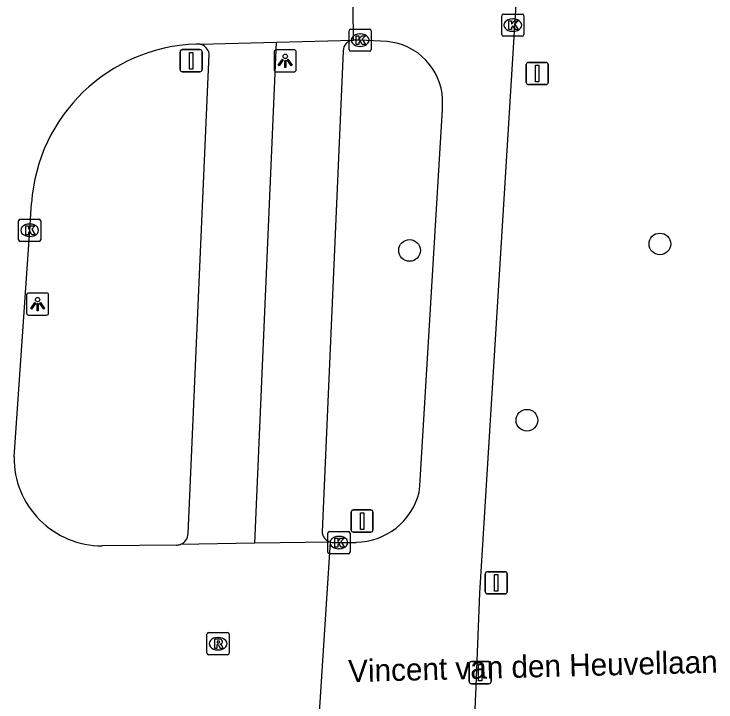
# Model space of a CAD drawing. Extents: x 161477 to 163040, y 383680 to 384868.
# Drawn here: x 161516.43 to 161548.07, y 384119.51 to 384150.53 of the extents above; entities that cross this region are included whole.
import ezdxf

# ---------------------------------------------------------------- set-up
doc = ezdxf.new("R2010")
doc.units = 0
for name, color, linetype in [('IMGEO_Afsluitpaal', 7, 'Continuous'), ('IMGEO_Boom', 7, 'Continuous'), ('IMGEO_Fietspad_open', 7, 'Continuous'), ('IMGEO_Kolk', 7, 'Continuous'), ('IMGEO_Lichtpunt', 7, 'Continuous'), ('IMGEO_Openbare_ruimte_label', 7, 'Continuous'), ('IMGEO_Rijbaan_lokaal_gesloten', 7, 'Continuous'), ('IMGEO_Rioolput', 7, 'Continuous'), ('IMGEO_Verkeersbordpaal', 7, 'Continuous'), ('IMGEO_Vlaggenmast', 7, 'Continuous'), ('IMGEO_Voetpad_open', 7, 'Continuous')]:
    doc.layers.add(name, color=color, linetype=linetype)

msp = doc.modelspace()

# ---------------------------------------------------------------- linework, layer by layer
at = {"layer": 'IMGEO_Afsluitpaal'}
for p, q in [((161537.045, 384121.33), (161537.835, 384121.33)), ((161537.835, 384121.33), (161537.045, 384121.33)), ((161536.945, 384120.43), (161536.945, 384121.23)), ((161536.945, 384121.23), (161536.945, 384120.43)), ((161537.935, 384121.23), (161537.935, 384120.43)), ((161537.935, 384120.43), (161537.935, 384121.23)), ((161537.835, 384120.33), (161537.045, 384120.33)), ((161537.045, 384120.33), (161537.835, 384120.33))]:
    msp.add_line(p, q, dxfattribs=at)
msp.add_lwpolyline([(161537.365, 384121.205), (161537.515, 384121.205), (161537.515, 384120.455), (161537.365, 384120.455), (161537.365, 384121.205)], dxfattribs=at)
for centre, start, end in [((161537.045, 384121.23), 90, 180), ((161537.045, 384121.23), 90, 180), ((161537.835, 384121.23), 0, 90), ((161537.835, 384121.23), 360, 90), ((161537.045, 384120.43), 180, 270), ((161537.045, 384120.43), 180, 270), ((161537.835, 384120.43), 270, 0), ((161537.835, 384120.43), 270, 0)]:
    msp.add_arc(centre, 0.1, start, end, dxfattribs=at)
at = {"layer": 'IMGEO_Boom'}
for centre in [(161545.537, 384140.162), (161534.259, 384139.873), (161539.548, 384132.212)]:
    msp.add_circle(centre, 0.489, dxfattribs=at)
at = {"layer": 'IMGEO_Fietspad_open'}
for points in [[(161527.282, 384126.677), (161528.268, 384149.264)], [(161524.274, 384127.108), (161525.225, 384148.724)]]:
    msp.add_lwpolyline(points, dxfattribs=at)
for centre, radius, start, end in [((161524.716, 384148.668), 0.512, 6.3303, 78.8532), ((161523.751, 384127.105), 0.523, 288.6131, 0.3768)]:
    msp.add_arc(centre, radius, start, end, dxfattribs=at)
at = {"layer": 'IMGEO_Kolk'}
for p, q in [((161538.41, 384149.606), (161538.41, 384150.458)), ((161538.485, 384150.532), (161539.337, 384150.532)), ((161539.411, 384150.458), (161539.411, 384149.606)), ((161538.898, 384150.312), (161538.923, 384150.312)), ((161531.604, 384149.853), (161532.456, 384149.853)), ((161531.529, 384148.927), (161531.529, 384149.779)), ((161532.017, 384149.633), (161532.042, 384149.633)), ((161532.53, 384149.779), (161532.53, 384148.927)), ((161539.337, 384149.532), (161538.485, 384149.532)), ((161538.921, 384149.752), (161538.896, 384149.752)), ((161532.456, 384148.853), (161531.604, 384148.853)), ((161532.04, 384149.073), (161532.015, 384149.073)), ((161516.714, 384141.279), (161517.566, 384141.279)), ((161516.639, 384140.353), (161516.639, 384141.205)), ((161517.127, 384141.059), (161517.152, 384141.059)), ((161517.64, 384141.205), (161517.64, 384140.353)), ((161517.15, 384140.499), (161517.125, 384140.499)), ((161517.566, 384140.279), (161516.714, 384140.279)), ((161530.574, 384126.269), (161530.574, 384127.121)), ((161530.649, 384127.195), (161531.501, 384127.195)), ((161531.575, 384127.121), (161531.575, 384126.269)), ((161531.062, 384126.975), (161531.087, 384126.975)), ((161531.085, 384126.415), (161531.06, 384126.415)), ((161531.501, 384126.195), (161530.649, 384126.195))]:
    msp.add_line(p, q, dxfattribs=at)
for points in [[(161538.41, 384149.606), (161538.41, 384150.458)], [(161538.485, 384150.532), (161539.337, 384150.532)], [(161539.411, 384150.458), (161539.411, 384149.606)], [(161538.731, 384150.232), (161538.854, 384150.232), (161538.854, 384150.081), (161538.984, 384150.232), (161539.148, 384150.232), (161539.002, 384150.081), (161539.155, 384149.832), (161539.003, 384149.832), (161538.918, 384149.996), (161538.854, 384149.929), (161538.854, 384149.832), (161538.731, 384149.832), (161538.731, 384150.232)], [(161531.604, 384149.853), (161532.456, 384149.853)], [(161531.529, 384148.927), (161531.529, 384149.779)], [(161531.85, 384149.553), (161531.973, 384149.553), (161531.973, 384149.402), (161532.103, 384149.553), (161532.267, 384149.553), (161532.121, 384149.402), (161532.274, 384149.153), (161532.122, 384149.153), (161532.037, 384149.317), (161531.973, 384149.25), (161531.973, 384149.153), (161531.85, 384149.153), (161531.85, 384149.553)], [(161532.53, 384149.779), (161532.53, 384148.927)], [(161539.337, 384149.532), (161538.485, 384149.532)], [(161532.456, 384148.853), (161531.604, 384148.853)], [(161516.714, 384141.279), (161517.566, 384141.279)], [(161516.639, 384140.353), (161516.639, 384141.205)], [(161516.96, 384140.979), (161517.083, 384140.979), (161517.083, 384140.828), (161517.213, 384140.979), (161517.377, 384140.979), (161517.231, 384140.828), (161517.384, 384140.579), (161517.232, 384140.579), (161517.147, 384140.743), (161517.083, 384140.676), (161517.083, 384140.579), (161516.96, 384140.579), (161516.96, 384140.979)], [(161517.64, 384141.205), (161517.64, 384140.353)], [(161517.566, 384140.279), (161516.714, 384140.279)], [(161530.574, 384126.269), (161530.574, 384127.121)], [(161530.649, 384127.195), (161531.501, 384127.195)], [(161531.575, 384127.121), (161531.575, 384126.269)], [(161530.895, 384126.895), (161531.018, 384126.895), (161531.018, 384126.744), (161531.148, 384126.895), (161531.312, 384126.895), (161531.166, 384126.744), (161531.319, 384126.495), (161531.167, 384126.495), (161531.082, 384126.659), (161531.018, 384126.592), (161531.018, 384126.495), (161530.895, 384126.495), (161530.895, 384126.895)], [(161531.501, 384126.195), (161530.649, 384126.195)]]:
    msp.add_lwpolyline(points, dxfattribs=at)
for centre, start, end in [((161538.487, 384150.456), 91.552, 178.448), ((161538.487, 384150.456), 91.552, 178.448), ((161539.335, 384150.456), 1.552, 88.448), ((161539.335, 384150.456), 1.552, 88.448), ((161531.606, 384149.777), 91.552, 178.448), ((161531.606, 384149.777), 91.552, 178.448), ((161532.454, 384149.777), 1.552, 88.448), ((161532.454, 384149.777), 1.552, 88.448), ((161538.487, 384149.608), 181.552, 268.448), ((161538.487, 384149.608), 181.552, 268.448), ((161539.335, 384149.608), 271.552, 358.448), ((161539.335, 384149.608), 271.552, 358.448), ((161531.606, 384148.929), 181.552, 268.448), ((161531.606, 384148.929), 181.552, 268.448), ((161532.454, 384148.929), 271.552, 358.448), ((161532.454, 384148.929), 271.552, 358.448), ((161516.716, 384141.203), 91.552, 178.448), ((161516.716, 384141.203), 91.552, 178.448), ((161517.564, 384141.203), 1.552, 88.448), ((161517.564, 384141.203), 1.552, 88.448), ((161516.716, 384140.355), 181.552, 268.448), ((161516.716, 384140.355), 181.552, 268.448), ((161517.564, 384140.355), 271.552, 358.448), ((161517.564, 384140.355), 271.552, 358.448), ((161530.651, 384127.119), 91.552, 178.448), ((161530.651, 384127.119), 91.552, 178.448), ((161531.499, 384127.119), 1.552, 88.448), ((161531.499, 384127.119), 1.552, 88.448), ((161530.651, 384126.271), 181.552, 268.448), ((161530.651, 384126.271), 181.552, 268.448), ((161531.499, 384126.271), 271.552, 358.448), ((161531.499, 384126.271), 271.552, 358.448)]:
    msp.add_arc(centre, 0.0765, start, end, dxfattribs=at)
for centre, major_axis, ratio, start_param, end_param in [((161538.897, 384150.032), (-0.387, 0.002), 0.722429, 4.712389, 7.853982), ((161538.922, 384150.032), (-0.39, 0.002), 0.717154, 1.570796, 4.712389), ((161532.016, 384149.353), (-0.387, 0.002), 0.722429, 4.712389, 7.853982), ((161532.041, 384149.353), (-0.39, 0.002), 0.717154, 1.570796, 4.712389), ((161517.126, 384140.779), (-0.387, 0.002), 0.722429, 4.712389, 7.853982), ((161517.151, 384140.779), (-0.39, 0.002), 0.717154, 1.570796, 4.712389), ((161531.061, 384126.695), (-0.387, 0.002), 0.722429, 4.712389, 7.853982), ((161531.086, 384126.695), (-0.39, 0.002), 0.717154, 1.570796, 4.712389)]:
    msp.add_ellipse(centre, major_axis=major_axis, ratio=ratio, start_param=start_param, end_param=end_param, dxfattribs=at)
at = {"layer": 'IMGEO_Lichtpunt'}
for p, q in [((161529.057, 384148.922), (161528.249, 384148.922)), ((161529.057, 384148.922), (161528.249, 384148.922)), ((161528.155, 384148.827), (161528.155, 384148.02)), ((161528.155, 384148.827), (161528.155, 384148.02)), ((161529.151, 384148.02), (161529.151, 384148.827)), ((161529.151, 384148.02), (161529.151, 384148.827)), ((161528.249, 384147.926), (161529.057, 384147.926)), ((161528.249, 384147.926), (161529.057, 384147.926)), ((161516.997, 384137.856), (161516.997, 384137.049)), ((161516.997, 384137.856), (161516.997, 384137.049)), ((161517.899, 384137.951), (161517.091, 384137.951)), ((161517.899, 384137.951), (161517.091, 384137.951)), ((161517.993, 384137.049), (161517.993, 384137.856)), ((161517.993, 384137.049), (161517.993, 384137.856)), ((161517.091, 384136.955), (161517.899, 384136.955)), ((161517.091, 384136.955), (161517.899, 384136.955))]:
    msp.add_line(p, q, dxfattribs=at)
for points in [[(161528.529, 384148.491), (161528.568, 384148.463), (161528.38, 384148.201), (161528.342, 384148.228), (161528.529, 384148.491)], [(161528.631, 384148.443), (161528.678, 384148.443), (161528.678, 384148.121), (161528.631, 384148.121), (161528.631, 384148.443)], [(161528.741, 384148.463), (161528.779, 384148.49), (161528.966, 384148.228), (161528.927, 384148.2), (161528.741, 384148.463)], [(161517.371, 384137.52), (161517.41, 384137.492), (161517.222, 384137.23), (161517.184, 384137.257), (161517.371, 384137.52)], [(161517.473, 384137.472), (161517.52, 384137.472), (161517.52, 384137.15), (161517.473, 384137.15), (161517.473, 384137.472)], [(161517.583, 384137.492), (161517.621, 384137.519), (161517.808, 384137.257), (161517.769, 384137.229), (161517.583, 384137.492)]]:
    msp.add_lwpolyline(points, dxfattribs=at)
for centre in [(161528.654, 384148.625), (161517.496, 384137.654)]:
    msp.add_circle(centre, 0.0994, dxfattribs=at)
for centre, start, end in [((161528.249, 384148.827), 90, 180), ((161528.249, 384148.827), 90, 180), ((161529.057, 384148.827), 0, 90), ((161529.057, 384148.827), 0, 90), ((161528.249, 384148.02), 180, 270), ((161528.249, 384148.02), 180, 270), ((161529.057, 384148.02), 270, 0), ((161529.057, 384148.02), 270, 360), ((161517.091, 384137.856), 90, 180), ((161517.091, 384137.856), 90, 180), ((161517.899, 384137.856), 0, 90), ((161517.899, 384137.856), 0, 90), ((161517.091, 384137.049), 180, 270), ((161517.091, 384137.049), 180, 270), ((161517.899, 384137.049), 270, 0), ((161517.899, 384137.049), 270, 360)]:
    msp.add_arc(centre, 0.0946, start, end, dxfattribs=at)
at = {"layer": 'IMGEO_Rijbaan_lokaal_gesloten'}
for points in [[(161531.725, 384149.358), (161531.642, 384158.109)], [(161539.082, 384151.455), (161537.405, 384124.413), (161537.225, 384119.825), (161537.21, 384119.595), (161537.167, 384118.119)], [(161524.815, 384149.17), (161528.268, 384149.264)], [(161528.268, 384149.264), (161531.725, 384149.358)], [(161533.25, 384149.288), (161532.03, 384149.353), (161531.793, 384149.36), (161531.759, 384149.36), (161531.725, 384149.358)], [(161534.686, 384128.956), (161534.722, 384129.256), (161535.738, 384146.227), (161535.746, 384146.688)], [(161516.434, 384130.556), (161517.14, 384140.779), (161517.224, 384142.004)], [(161530.697, 384126.716), (161527.282, 384126.677)], [(161530.064, 384116.948), (161530.697, 384126.716)], [(161530.841, 384126.7), (161531.075, 384126.695), (161531.85, 384126.707)], [(161523.75, 384126.582), (161520.406, 384126.549)], [(161527.282, 384126.677), (161523.918, 384126.609)]]:
    msp.add_lwpolyline(points, dxfattribs=at)
for centre, radius, start, end in [((161524.896, 384141.489), 7.689, 91.8843, 176.1601), ((161524.717, 384148.647), 0.532, 79.3661, 97.9695), ((161533.014, 384146.564), 2.735, 2.6081, 85.0536), ((161520.403, 384130.518), 3.969, 179.456, 270.0414), ((161531.793, 384129.692), 2.985, 271.0957, 345.7344), ((161530.826, 384127.219), 0.519, 255.6373, 271.6824), ((161523.747, 384127.136), 0.554, 270.2901, 287.9703)]:
    msp.add_arc(centre, radius, start, end, dxfattribs=at)
at = {"layer": 'IMGEO_Rioolput'}
for p, q in [((161525.204, 384122.636), (161526.056, 384122.636)), ((161525.129, 384121.71), (161525.129, 384122.562)), ((161525.617, 384122.416), (161525.642, 384122.416)), ((161526.13, 384122.562), (161526.13, 384121.71)), ((161526.056, 384121.636), (161525.204, 384121.636)), ((161525.64, 384121.856), (161525.615, 384121.856))]:
    msp.add_line(p, q, dxfattribs=at)
for points in [[(161525.204, 384122.636), (161526.056, 384122.636)], [(161525.129, 384121.71), (161525.129, 384122.562)], [(161525.718, 384122.334), (161525.466, 384122.336), (161525.466, 384121.936)], [(161526.13, 384122.562), (161526.13, 384121.71)], [(161525.466, 384121.936), (161525.59, 384121.936), (161525.59, 384122.098), (161525.601, 384122.098)], [(161525.644, 384122.255), (161525.59, 384122.255), (161525.59, 384122.174)], [(161525.59, 384122.174), (161525.642, 384122.174)], [(161525.648, 384122.069), (161525.719, 384121.936), (161525.859, 384121.936), (161525.794, 384122.062)], [(161526.056, 384121.636), (161525.204, 384121.636)]]:
    msp.add_lwpolyline(points, dxfattribs=at)
for centre, radius, start, end in [((161525.206, 384122.56), 0.0765, 91.552, 178.448), ((161525.206, 384122.56), 0.0765, 91.552, 178.448), ((161526.054, 384122.56), 0.0765, 1.552, 88.448), ((161526.054, 384122.56), 0.0765, 1.552, 88.448), ((161525.717, 384122.224), 0.109, 350.3612, 89.416), ((161525.6, 384122.045), 0.0533, 26.0293, 88.6989), ((161525.626, 384122.363), 0.19, 274.7715, 282.9687), ((161525.65, 384122.159), 0.0964, 77.0061, 93.1865), ((161525.664, 384122.216), 0.0378, 276.6634, 79.6772), ((161525.715, 384122.224), 0.112, 277.5842, 350.9817), ((161525.699, 384122.009), 0.108, 29.5134, 73.7905), ((161525.206, 384121.712), 0.0765, 181.552, 268.448), ((161525.206, 384121.712), 0.0765, 181.552, 268.448), ((161526.054, 384121.712), 0.0765, 271.552, 358.448), ((161526.054, 384121.712), 0.0765, 271.552, 358.448)]:
    msp.add_arc(centre, radius, start, end, dxfattribs=at)
for centre, major_axis, ratio, start_param, end_param in [((161525.616, 384122.136), (-0.387, 0.002), 0.722429, 4.712389, 7.853982), ((161525.641, 384122.136), (-0.39, 0.002), 0.717154, 1.570796, 4.712389)]:
    msp.add_ellipse(centre, major_axis=major_axis, ratio=ratio, start_param=start_param, end_param=end_param, dxfattribs=at)
at = {"layer": 'IMGEO_Verkeersbordpaal'}
for p, q in [((161524.017, 384148.926), (161524.807, 384148.926)), ((161524.807, 384148.926), (161524.017, 384148.926)), ((161523.917, 384148.026), (161523.917, 384148.826)), ((161523.917, 384148.826), (161523.917, 384148.026)), ((161524.907, 384148.826), (161524.907, 384148.026)), ((161524.907, 384148.026), (161524.907, 384148.826)), ((161524.807, 384147.926), (161524.017, 384147.926)), ((161524.017, 384147.926), (161524.807, 384147.926)), ((161531.62, 384127.266), (161531.62, 384128.066)), ((161531.62, 384128.066), (161531.62, 384127.266)), ((161531.72, 384128.166), (161532.51, 384128.166)), ((161532.51, 384128.166), (161531.72, 384128.166)), ((161532.61, 384128.066), (161532.61, 384127.266)), ((161532.61, 384127.266), (161532.61, 384128.066)), ((161532.51, 384127.166), (161531.72, 384127.166)), ((161531.72, 384127.166), (161532.51, 384127.166)), ((161537.672, 384124.484), (161537.672, 384125.284)), ((161537.672, 384125.284), (161537.672, 384124.484)), ((161537.772, 384125.384), (161538.562, 384125.384)), ((161538.562, 384125.384), (161537.772, 384125.384)), ((161538.662, 384125.284), (161538.662, 384124.484)), ((161538.662, 384124.484), (161538.662, 384125.284)), ((161538.562, 384124.384), (161537.772, 384124.384)), ((161537.772, 384124.384), (161538.562, 384124.384))]:
    msp.add_line(p, q, dxfattribs=at)
for points in [[(161524.337, 384148.801), (161524.487, 384148.801), (161524.487, 384148.051), (161524.337, 384148.051), (161524.337, 384148.801)], [(161532.04, 384128.041), (161532.19, 384128.041), (161532.19, 384127.291), (161532.04, 384127.291), (161532.04, 384128.041)], [(161538.092, 384125.259), (161538.242, 384125.259), (161538.242, 384124.509), (161538.092, 384124.509), (161538.092, 384125.259)]]:
    msp.add_lwpolyline(points, dxfattribs=at)
for centre, start, end in [((161524.017, 384148.826), 90, 180), ((161524.017, 384148.826), 90, 180), ((161524.807, 384148.826), 0, 90), ((161524.807, 384148.826), 360, 90), ((161524.017, 384148.026), 180, 270), ((161524.017, 384148.026), 180, 270), ((161524.807, 384148.026), 270, 0), ((161524.807, 384148.026), 270, 0), ((161531.72, 384128.066), 90, 180), ((161531.72, 384128.066), 90, 180), ((161532.51, 384128.066), 0, 90), ((161532.51, 384128.066), 360, 90), ((161531.72, 384127.266), 180, 270), ((161531.72, 384127.266), 180, 270), ((161532.51, 384127.266), 270, 0), ((161532.51, 384127.266), 270, 0), ((161537.772, 384125.284), 90, 180), ((161537.772, 384125.284), 90, 180), ((161538.562, 384125.284), 0, 90), ((161538.562, 384125.284), 360, 90), ((161537.772, 384124.484), 180, 270), ((161537.772, 384124.484), 180, 270), ((161538.562, 384124.484), 270, 0), ((161538.562, 384124.484), 270, 0)]:
    msp.add_arc(centre, 0.1, start, end, dxfattribs=at)
at = {"layer": 'IMGEO_Vlaggenmast'}
for p, q in [((161539.517, 384147.45), (161539.517, 384148.25)), ((161539.517, 384148.25), (161539.517, 384147.45)), ((161539.617, 384148.35), (161540.407, 384148.35)), ((161540.407, 384148.35), (161539.617, 384148.35)), ((161540.507, 384148.25), (161540.507, 384147.45)), ((161540.507, 384147.45), (161540.507, 384148.25)), ((161540.407, 384147.35), (161539.617, 384147.35)), ((161539.617, 384147.35), (161540.407, 384147.35))]:
    msp.add_line(p, q, dxfattribs=at)
msp.add_lwpolyline([(161539.937, 384148.225), (161540.087, 384148.225), (161540.087, 384147.475), (161539.937, 384147.475), (161539.937, 384148.225)], dxfattribs=at)
for centre, start, end in [((161539.617, 384148.25), 90, 180), ((161539.617, 384148.25), 90, 180), ((161540.407, 384148.25), 0, 90), ((161540.407, 384148.25), 360, 90), ((161539.617, 384147.45), 180, 270), ((161539.617, 384147.45), 180, 270), ((161540.407, 384147.45), 270, 0), ((161540.407, 384147.45), 270, 0)]:
    msp.add_arc(centre, 0.1, start, end, dxfattribs=at)
at = {"layer": 'IMGEO_Voetpad_open'}
msp.add_lwpolyline([(161531.263, 384148.863), (161530.314, 384127.202)], dxfattribs=at)
for centre, radius, start, end in [((161531.773, 384148.851), 0.51, 95.3479, 178.6019), ((161530.822, 384127.208), 0.508, 180.7023, 255.7786)]:
    msp.add_arc(centre, radius, start, end, dxfattribs=at)

# ---------------------------------------------------------------- texts
at = {"layer": 'IMGEO_Openbare_ruimte_label'}
msp.add_text('Vincent van den Heuvellaan', height=1, rotation=1.4894, dxfattribs=at).set_placement((161531.505, 384120.401))

doc.saveas('drawing.dxf')
